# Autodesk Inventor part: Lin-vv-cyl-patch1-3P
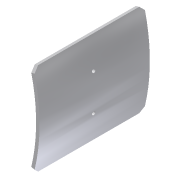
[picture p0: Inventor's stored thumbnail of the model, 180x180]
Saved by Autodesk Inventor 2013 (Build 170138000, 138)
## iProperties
Created: 2012-05
Part Number: Lin-vv-cyl-patch1-3P
Material: Stainless Steel, 316
Description: CYLINDER PATCH
Document SubType Name: Sheet Metal
Designer: Henneborn
Manufacturer: Standard
Standards Organization: Custom
Mass: 6803.9 g
Surface Area: 1921.93 cm^2
Volume: 861.253 cm^3
Density: 7.9 g/cm^3
Flat Pattern Width: 31.8512 cm
Flat Pattern Length: 35.3879 cm
Flat Pattern Area: 1127.15 cm^2
Sheet Metal Rule: Default
Sheet Metal Width: 12.540 in
Sheet Metal Length: 13.932 in
Sheet Metal Area: 174.708 in^2
Rohmasse: 12" x 10" x 0,375" THK.PLATE
Author: vm
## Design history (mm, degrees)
sketch "Sketch1"
  geometry: L1 (0, 0)-(475.356, 127.371); L2 (0, 0)-(475.356, -127.371); L3 (-688.975, 0)-(688.975, 0) reference; L4 (475.356, 127.371)-(466.156, 124.906); L5 (475.356, -127.371)-(466.156, -124.906); A1 r 482.6 centre (0, 0) between (466.156, 124.906) and (466.156, -124.906); A2 r 492.125 centre (0, 0) between (475.356, 127.371) and (475.356, -127.371); 1 further point
  constraints: 8 end point, 4 point on circle, 2 centre point, 2 coincident, 2 point on line
  dimensions: "d0" = 965.2 diameter of A1; "d1" = 9.525 radial gap between concentric circles of A2 A1; "d2" = 15 deg angle of L1 L3; "d3" = 15 deg angle of L2 L3
extrude "Extrusion1" join sketch "Sketch1" stored distance "d4" = 304.8; taper "d5" = 0 deg
chamfer "Chamfer1" distance "d6" = 12.7; stored, may be unused: second distance "d7" = 3.175, angle "d8" = 45 deg
sketch "Sketch9"
  geometry: L1 (0, 6.668)-(0, -6.668) reference; L2 (-77.788, 0)-(77.788, 0) reference; C1 r 4.763 at (50.8, 0); C2 r 4.763 at (-50.8, 0)
  constraints: 2 centre point, 2 point on line
  dimensions: "d56" = 9.525 diameter of C1; "d57" = 9.525 diameter of C2; "d58" = 50.8 distance from line of L1 C2.centre; "d59" = 50.8 distance from line of L1 C1.centre
extrude "Extrusion3" cut sketch "Sketch9" stored distance "d60" = 25.4; taper "d61" = 0 deg
body "Solid1"
node "FlatPattern"
feature "FlatPatternExtrusion2" dims "d0" = 9.525 (derived)
other parameters: "Thickness" = 9.525, "BendRadius" = 9.525 (= Thickness), "BendReliefWidth" = 9.525 (= Thickness), "BendReliefDepth" = 4.7625 (= 0.5 x Thickness), "CornerReliefSize" = 38.1 (= 4 x Thickness), "SeamGap" = 0.00508, "MinimumRemnant" = 19.05 (= 2 x Thickness), "TransitionRadius" = 9.525 (= BendRadius), "JacobiRadiusSize" = 9.525 (derived), "GapSize" = 9.525 (derived)
